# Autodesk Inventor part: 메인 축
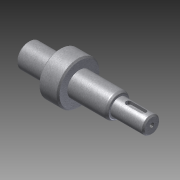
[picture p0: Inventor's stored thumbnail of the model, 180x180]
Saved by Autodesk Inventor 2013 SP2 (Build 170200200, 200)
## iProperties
Created: 2016-04
Part Number: 메인 축
Document SubType Name: Modeling
Designer: mdu
Density: 7.86 g/cm^3
Mass: 230.24 g
Surface Area: 74.3518 cm^2
Volume: 29.2926 cm^3
Material: 강철, 연강
Author: mdu
Revision Number: 1
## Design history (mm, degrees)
sketch "스케치1"
  geometry: L1 (10.497, -57.5)-(97.497, -57.5); L2 (10.497, -66)-(32.497, -66); L3 (32.497, -72.5)-(46.5, -72.5); L4 (46.5, -66)-(74.497, -66); L5 (97.497, -63.5)-(97.497, -57.5); L6 (10.497, -66)-(10.497, -57.5); L7 (46.5, -69.749)-(46.5, -45.251) reference; L8 (46.5, -72.5)-(46.5, -66); L9 (32.497, -72.5)-(32.497, -66); L10 (32.497, -35)-(32.497, -80) reference; L11 (97.497, -63.5)-(74.497, -63.5); L12 (74.497, -63.5)-(74.497, -66); 3 further points
  constraints: 20 end point, 4 perpendicular, 3 point on line, 2 parallel, 1 collinear, 1 horizontal, 1 midpoint
  dimensions: "d0" = 17 diameter of L4 L1; "d1" = 30 diameter of L3 L1; "d2" = 22 distance of L2.start L2.end; "d5" = 17 diameter of L2 L1; "d19" = 65 distance between parallel lines of L5 L9; "d21" = 50.99692 distance between parallel lines of L5 L8 (derived); "d22" = 23 distance between parallel lines of L5 L12; "d23" = 12 diameter of L11 L1
revolve "회전1" sketch "스케치1" stored, may be unused: angle "d4" = 90 deg
chamfer "모따기1" distance "d6" = 1; stored, may be unused: second distance "d7" = 2, angle "d8" = 45 deg
node "작업 평면1"
sketch "스케치2"
  geometry: L1 (10.497, -65)-(10.497, -50) reference; L2 (16.997, -55)-(25.997, -55); L3 (25.997, -60)-(16.997, -60); A1 r 2.5 centre (25.997, -57.5) between (25.997, -60) and (25.997, -55); A2 r 2.5 centre (16.997, -57.5) between (16.997, -55) and (16.997, -60); 2 further points
  constraints: 4 end point, 4 point on circle, 4 tangent, 2 centre point, 1 horizontal alignment, 1 midpoint, 1 parallel, 1 perpendicular
  dimensions: "d9" = 5 distance between parallel lines of L3 L2; "d10" = 14 dimension on A1 A2; "d11" = 4 distance edge to line of A2 L1
extrude "돌출1" cut sketch "스케치2" distance "d12" = 3; taper "d13" = 0 deg
node "작업 평면2"
sketch "스케치3"
  geometry: L1 (91.497, -55.5)-(81.497, -55.5); L2 (81.497, -59.5)-(91.497, -59.5); L3 (97.497, -52.5)-(97.497, -62.5) reference; A1 r 2 centre (81.497, -57.5) between (81.497, -55.5) and (81.497, -59.5); A2 r 2 centre (91.497, -57.5) between (91.497, -59.5) and (91.497, -55.5); 4 further points
  constraints: 4 end point, 4 point on circle, 4 tangent, 2 centre point, 2 horizontal, 2 point on line, 1 horizontal alignment, 1 midpoint, 1 vertical alignment
  dimensions: "d32" = 14 dimension on A2 A1; "d34" = 4 distance edge to line of A2 L3; "d35" = 4 distance between parallel lines of L2 L1
extrude "돌출2" cut sketch "스케치3" distance "d16" = 2.5; taper "d17" = 0 deg
sketch "스케치4"
  geometry: L1 (74.497, -50.05)-(72.678, -49); L2 (74.497, -49)-(46.5, -49) reference; L3 (74.497, -49)-(74.497, -66) reference; L4 (74.497, -66)-(46.5, -66) reference; L5 (74.497, -57.5)-(60.711, -57.5); 1 further point
  constraints: 4 end point, 2 point on line, 1 midpoint, 1 parallel
  dimensions: "d24" = 14.9 diameter of L1.start L5; "d26" = 30 deg angle of L2 L1
revolve "회전2" sketch "스케치4" stored, may be unused: angle "d28" = 90 deg
fillet "모깎기1" dims "d29" = 1
fillet "모깎기2" dims "d30" = 2
hole "구멍1" diameter "d38" = 3.242; stored, may be unused: countersink angle "d42" = 90 deg, drill point angle "d44" = 118 deg; dims "d39" = 8, "d40" = 4, "d41" = 2, "d43" = 10, "d45" = 10, "d46" = 10
node "솔리드1"
node "참조4"
node "참조5"
other parameters: "d20" = 6, "d47" = -8.5
